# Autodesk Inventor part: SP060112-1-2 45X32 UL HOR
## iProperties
Created: 2012-06
Part Number: SP060112-1-2 45X32 UL HOR
Material: Aluminum-6061
Description: PROFILE 45X32 UL
Document SubType Name: Modeling
Designer: Administrator
Stock Number: 20.1065 PROFILE 45X32 UL
Density: 2.71 g/cm^3
Mass: 972.653 g
Surface Area: 3469.15 cm^2
Volume: 358.913 cm^3
FINISH: CLEAR ANODIZED
Author: Administrator
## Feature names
1. Extrusion1
